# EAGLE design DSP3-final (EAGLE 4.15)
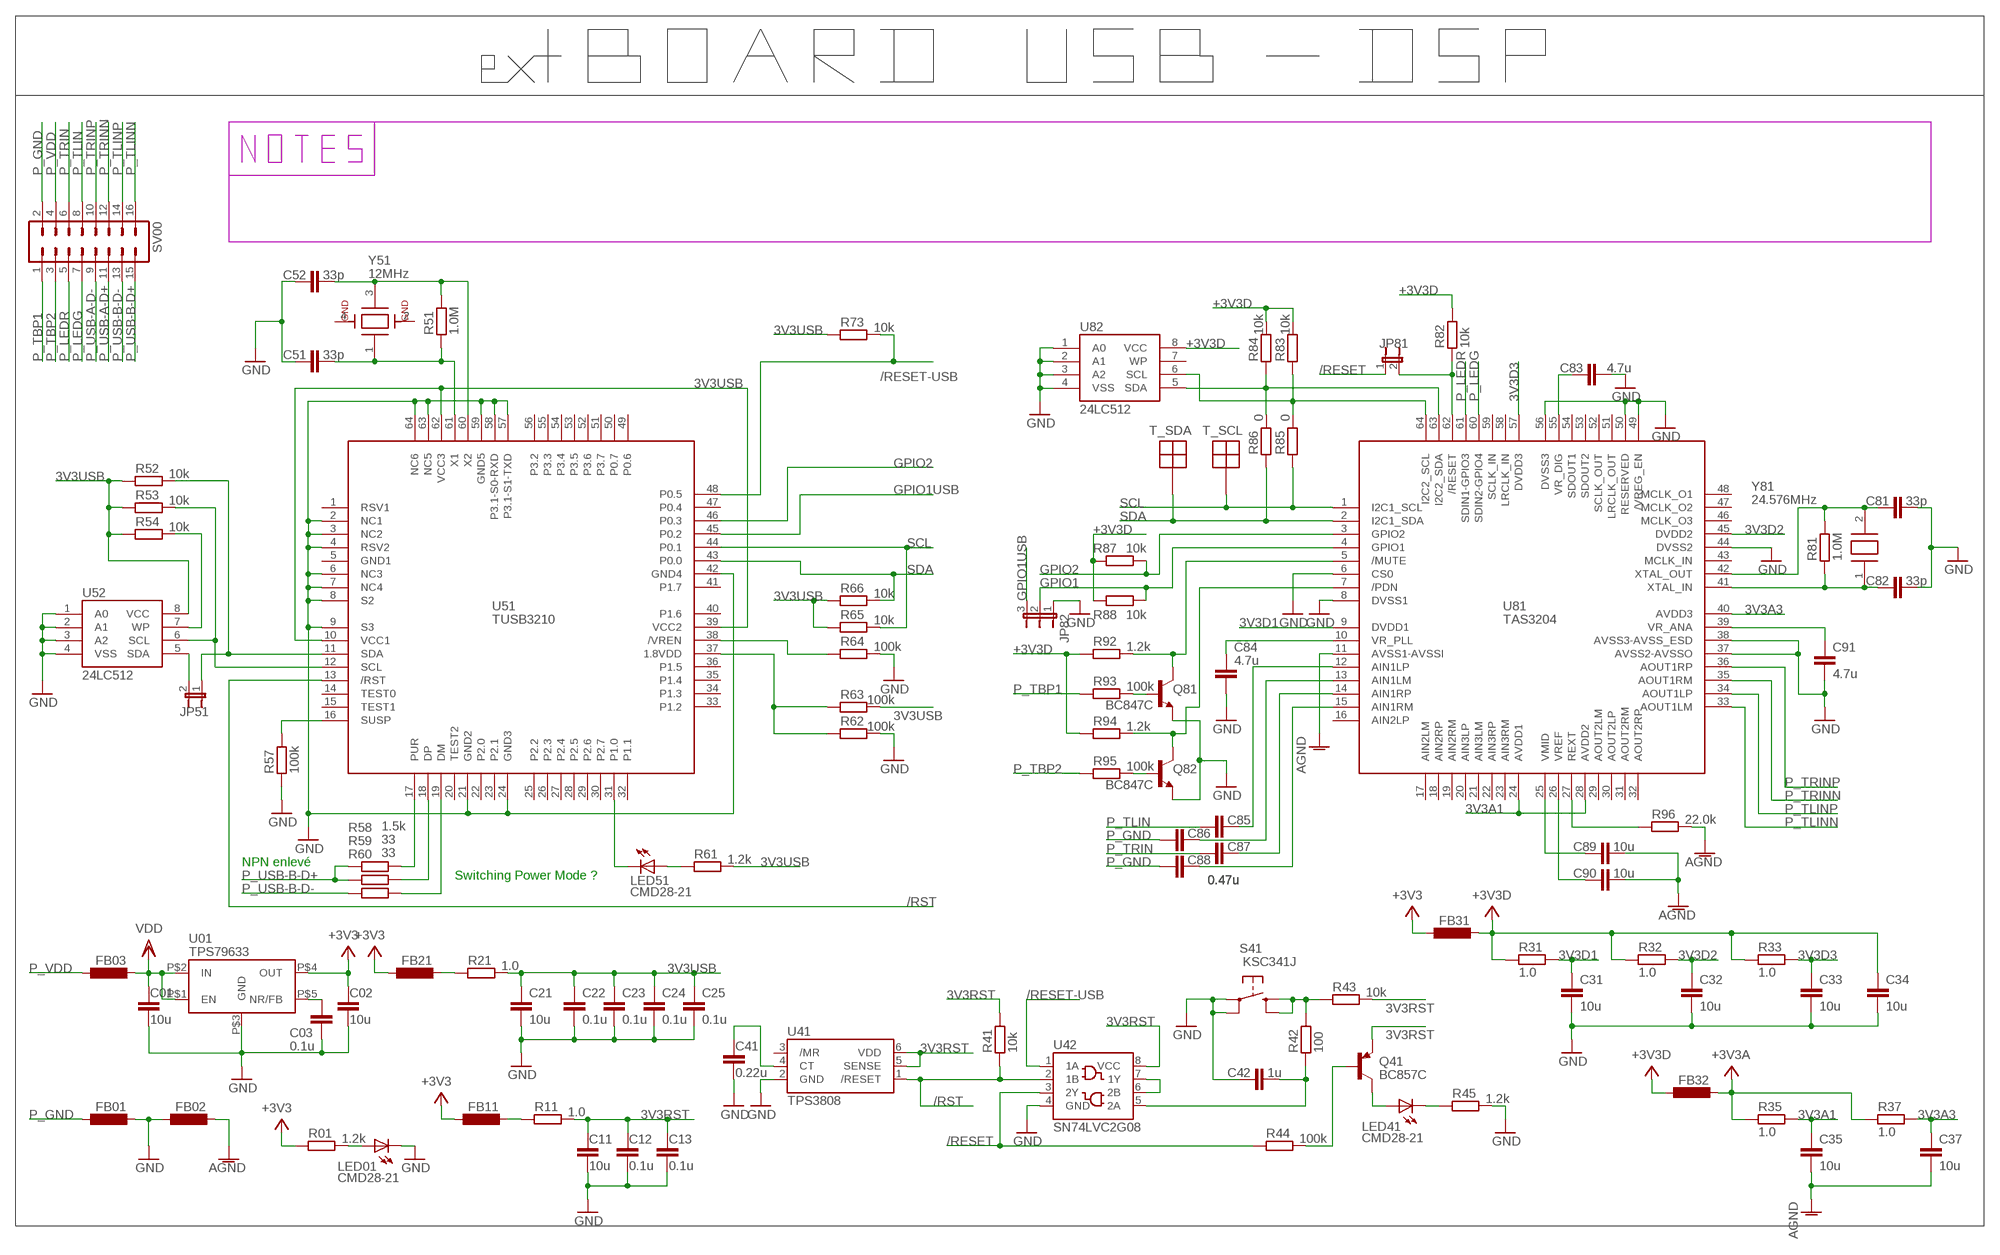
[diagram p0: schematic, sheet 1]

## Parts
C01  10u  C-EUC-EU-0603  [R0603]
C02  10u  C-EUC-EU-0603  [R0603]
C03  0.1u  C-EUC-EU-0603  [R0603]
C11  10u  C-EUC-EU-0603  [R0603]
C12  0.1u  C-EUC-EU-0603  [R0603]
C13  0.1u  C-EUC-EU-0603  [R0603]
C21  10u  C-EUC-EU-0603  [R0603]
C22  0.1u  C-EUC-EU-0603  [R0603]
C23  0.1u  C-EUC-EU-0603  [R0603]
C24  0.1u  C-EUC-EU-0603  [R0603]
C25  0.1u  C-EUC-EU-0603  [R0603]
C31  10u  C-EUC-EU-0603  [R0603]
C32  10u  C-EUC-EU-0603  [R0603]
C33  10u  C-EUC-EU-0603  [R0603]
C34  10u  C-EUC-EU-0603  [R0603]
C35  10u  C-EUC-EU-0603  [R0603]
C37  10u  C-EUC-EU-0603  [R0603]
C41  0.22u  C-EUC-EU-0603  [R0603]
C42  1u  C-EUC-EU-0603  [R0603]
C51  33p  C-EUC-EU-0603  [R0603]
C52  33p  C-EUC-EU-0603  [R0603]
C81  33p  C-EUC-EU-0603  [R0603]
C82  33p  C-EUC-EU-0603  [R0603]
C83  4.7u  C-EUC-EU-0603  [R0603]
C84  4.7u  C-EUC-EU-0603  [R0603]
C85  0.47u  C-EUC-EU-0603  [R0603]
C86  0.47u  C-EUC-EU-0603  [R0603]
C87  0.47u  C-EUC-EU-0603  [R0603]
C88  0.47u  C-EUC-EU-0603  [R0603]
C89  10u  C-EUC-EU-0603  [R0603]
C90  10u  C-EUC-EU-0603  [R0603]
C91  4.7u  C-EUC-EU-0603  [R0603]
FB01  L-EUFB-EU-1806  [FB1806]
FB02  L-EUFB-EU-1806  [FB1806]
FB03  L-EUFB-EU-1806  [FB1806]
FB11  L-EUFB-EU-1806  [FB1806]
FB21  L-EUFB-EU-1806  [FB1806]
FB31  L-EUFB-EU-1806  [FB1806]
FB32  L-EUFB-EU-1806  [FB1806]
JP51  JP1E  [JP1]
JP81  JP1E  [JP1]
JP82  JP2E  [JP2]
LED01  CMD28-21  [CMD28-21]
LED41  CMD28-21  [CMD28-21]
LED51  CMD28-21  [CMD28-21]
Q41  BC857C  BC857CSMD  [SOT23-BEC]
Q81  BC847C  BC847CSMD  [SOT23]
Q82  BC847C  BC847CSMD  [SOT23]
R01  1.2k  R-EUR-EU-0603  [R0603]
R11  1.0  R-EUR-EU-0603  [R0603]
R21  1.0  R-EUR-EU-0603  [R0603]
R31  1.0  R-EUR-EU-0603  [R0603]
R32  1.0  R-EUR-EU-0603  [R0603]
R33  1.0  R-EUR-EU-0603  [R0603]
R35  1.0  R-EUR-EU-0603  [R0603]
R37  1.0  R-EUR-EU-0603  [R0603]
R41  10k  R-EUR-EU-0603  [R0603]
R42  100  R-EUR-EU-0603  [R0603]
R43  10k  R-EUR-EU-0603  [R0603]
R44  100k  R-EUR-EU-0603  [R0603]
R45  1.2k  R-EUR-EU-0603  [R0603]
R51  1.0M  R-EUR-EU-0603  [R0603]
R52  10k  R-EUR-EU-0603  [R0603]
R53  10k  R-EUR-EU-0603  [R0603]
R54  10k  R-EUR-EU-0603  [R0603]
R57  100k  R-EUR-EU-0603  [R0603]
R58  1.5k  R-EUR-EU-0603  [R0603]
R59  33  R-EUR-EU-0603  [R0603]
R60  33  R-EUR-EU-0603  [R0603]
R61  1.2k  R-EUR-EU-0603  [R0603]
R62  100k  R-EUR-EU-0603  [R0603]
R63  100k  R-EUR-EU-0603  [R0603]
R64  100k  R-EUR-EU-0603  [R0603]
R65  10k  R-EUR-EU-0603  [R0603]
R66  10k  R-EUR-EU-0603  [R0603]
R73  10k  R-EUR-EU-0603  [R0603]
R81  1.0M  R-EUR-EU-0603  [R0603]
R82  10k  R-EUR-EU-0603  [R0603]
R83  10k  R-EUR-EU-0603  [R0603]
R84  10k  R-EUR-EU-0603  [R0603]
R85  0  R-EUR-EU-0603  [R0603]
R86  0  R-EUR-EU-0603  [R0603]
R87  10k  R-EUR-EU-0603  [R0603]
R88  10k  R-EUR-EU-0603  [R0603]
R92  1.2k  R-EUR-EU-0603  [R0603]
R93  100k  R-EUR-EU-0603  [R0603]
R94  1.2k  R-EUR-EU-0603  [R0603]
R95  100k  R-EUR-EU-0603  [R0603]
R96  22.0k  R-EUR-EU-0603  [R0603]
S41  KSC341J  [KSCTACTILEJ]
SV00  MA08-20.9MM  [MA08-2-0.9MM]
T_SCL  PICOT  [PICOT]
T_SDA  PICOT  [PICOT]
U01  TPS79633  TPS79633DDPAK-5  [DDPAK-5]
U41  TPS3808  TPS3808DBV  [SOT23-6]
U42  SN74LVC2G08  SN74LVC2G08DCT  [DCT8]
U51  TUSB3210  TUSB321010X10  [SQFP-S-10X10-64]
U52  24LC512  24LC512SOIC08SP  [SO08SP]
U81  TAS3204  TAS320410X10  [SQFP-S-10X10-64]
U82  24LC512  24LC512SOIC08SP  [SO08SP]
Y51  12MHz  ABMM2  [ABMM2]
Y81  24.576MHz  ABM3  [ABM3]

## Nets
3V3A1: C35.P$1 R35.P$2 U81.24(AVDD1) U81.28(AVDD2)
3V3A3: C37.P$1 R37.P$2 U81.40(AVDD3)
3V3D1: C31.P$1 R31.P$2 U81.9(DVDD1)
3V3D2: C32.P$1 R32.P$2 U81.45(DVDD2)
3V3D3: C33.P$1 R33.P$2 U81.57(DVDD3)
3V3RST: C11.P$1 C12.P$1 C13.P$1 Q41.E R11.P$2 R41.P$2 R43.P$2 U41.5(SENSE) U41.6(VDD) U42.8(VCC)
3V3USB: C21.P$1 C22.P$1 C23.P$1 C24.P$1 C25.P$1 R21.P$2 R52.P$1 R53.P$1 R54.P$1 R61.P$2 R63.P$2 R65.P$1 R66.P$1 R73.P$1 U51.10(VCC1) U51.39(VCC2) U51.62(VCC3) U52.8(VCC)
+3V3: C02.P$1 FB11.P$2 FB21.P$2 FB31.P$2 R01.P$1 U01.P$4(OUT)
+3V3A: FB32.P$1 R35.P$1 R37.P$1
+3V3D: C34.P$1 FB31.P$1 FB32.P$2 R31.P$1 R32.P$1 R33.P$1 R82.P$2 R83.P$2 R84.P$2 R87.P$1 R88.P$1 R92.P$1 R94.P$1 U82.8(VCC)
/RESET: JP81.1 R44.P$1 U42.3(2Y)
/RESET-USB: R73.P$2 U42.1(1A) U51.48(P0.5)
/RST: R41.P$1 U41.1(/RESET) U42.2(1B) U51.13(/RST)
AGND: C35.P$2 C37.P$2 C89.P$2 C90.P$2 FB02.P$1 R96.P$2 U81.11(AVSS1-AVSSI)
GND: C01.P$2 C02.P$2 C03.P$2 C11.P$2 C12.P$2 C13.P$2 C21.P$2 C22.P$2 C23.P$2 C24.P$2 C25.P$2 C31.P$2 C32.P$2 C33.P$2 C34.P$2 C41.P$2 C42.P$1 C51.P$1 C52.P$1 C81.P$2 C82.P$2 C83.P$2 C84.P$2 C91.P$2 FB01.P$1 FB02.P$2 JP82.1 LED01.P$1(C) Q81.2(E) Q82.2(E) R45.P$2 R57.P$1 R62.P$2 R64.P$2 S41.P$1(P) S41.P$4(P1) U01.P$3(GND) U41.2(GND) U42.4(GND) U51.2(NC1) U51.3(NC2) U51.4(RSV2) U51.6(NC3) U51.7(NC4) U51.8(S2) U51.9(S3) U51.21(GND2) U51.24(GND3) U51.42(GND4) U51.57(P3.1-S1-TXD) U51.58(P3.1-S0-RXD) U51.59(GND5) U51.63(NC5) U51.64(NC6) U52.1(A0) U52.2(A1) U52.3(A2) U52.4(VSS) U81.6(CS0) U81.8(DVSS1) U81.37(AVSS2-AVSSO) U81.38(AVSS3-AVSS_ESD) U81.44(DVSS2) U81.49(/VREG_EN) U81.50(RESERVED) U81.56(DVSS3) U82.1(A0) U82.2(A1) U82.3(A2) U82.4(VSS)
GPIO1: JP82.2 R88.P$2 U81.4(GPIO1)
GPIO1USB: JP82.3 U51.45(P0.2)
GPIO2: R87.P$2 U51.46(P0.3) U81.3(GPIO2)
N$1: C52.P$2 R51.P$2 U51.60(X2) Y51.3
N$2: JP51.1 R52.P$2 U51.11(SDA)
N$3: C51.P$2 R51.P$1 U51.61(X1) Y51.1
N$4: Q81.3(C) R92.P$2 U81.5(/MUTE)
N$6: R53.P$2 U51.12(SCL) U52.6(SCL)
N$7: R54.P$2 U52.7(WP)
N$8: R58.P$2 U51.17(PUR)
N$9: R59.P$2 U51.18(DP)
N$10: R60.P$2 U51.19(DM)
N$11: Q41.B R44.P$2
N$12: R96.P$1 U81.27(REXT)
N$13: R57.P$2 U51.16(SUSP)
N$14: LED51.P$1(C) U51.31(P1.0)
N$15: LED51.P$2(A) R61.P$1
N$16: R64.P$1 U51.38(/VREN)
N$17: R62.P$1 R63.P$1 U51.37(1.8VDD)
N$18: C41.P$1 U41.4(CT)
N$19: Q81.1(B) R93.P$2
N$20: Q82.1(B) R95.P$2
N$21: Q82.3(C) R94.P$2 U81.7(/PDN)
N$25: JP51.2 U52.5(SDA)
N$26: C03.P$1 U01.P$5(NR/FB)
N$29: C81.P$1 R81.P$2 U81.42(XTAL_OUT) Y81.2
N$31: C82.P$1 R81.P$1 U81.41(XTAL_IN) Y81.1
N$34: C84.P$1 U81.10(VR_PLL)
N$36: C91.P$1 U81.39(VR_ANA)
N$43: C83.P$1 U81.55(VR_DIG)
N$45: JP81.2 R82.P$1 U81.62(/RESET)
N$47: R84.P$1 R86.P$2 U81.63(I2C2_SDA) U82.5(SDA)
N$48: R83.P$1 R85.P$2 U81.64(I2C2_SCL) U82.6(SCL)
N$58: C89.P$1 U81.25(VMID)
N$59: C90.P$1 U81.26(VREF)
N$64: C85.P$1 U81.12(AIN1LP)
N$65: C86.P$1 U81.13(AIN1LM)
N$66: C87.P$1 U81.14(AIN1RP)
N$67: C88.P$1 U81.15(AIN1RM)
N$91: U42.6(2B) U42.7(1Y)
N$93: R42.P$2 R43.P$1 S41.P$2(S) S41.P$3(S1)
N$96: C42.P$2 R42.P$1 U42.5(2A)
N$98: LED41.P$2(A) Q41.C
N$99: LED41.P$1(C) R45.P$1
N$101: FB21.P$1 R21.P$1
N$110: LED01.P$2(A) R01.P$2
N$111: FB11.P$1 R11.P$1
P_GND: C86.P$2 C88.P$2 FB01.P$2 SV00.2
P_LEDG: SV00.7 U81.60(SDIN2-GPIO4)
P_LEDR: SV00.5 U81.61(SDIN1-GPIO3)
P_TBP1: R93.P$1 SV00.1
P_TBP2: R95.P$1 SV00.3
P_TLIN: C85.P$2 SV00.8
P_TLINN: SV00.16 U81.33(AOUT1LM)
P_TLINP: SV00.14 U81.34(AOUT1LP)
P_TRIN: C87.P$2 SV00.6
P_TRINN: SV00.12 U81.35(AOUT1RM)
P_TRINP: SV00.10 U81.36(AOUT1RP)
P_USB-A-D+: SV00.11
P_USB-A-D-: SV00.9
P_USB-B-D+: R58.P$1 R59.P$1 SV00.15
P_USB-B-D-: R60.P$1 SV00.13
P_VDD: FB03.P$2 SV00.4
SCL: R65.P$2 R85.P$1 T_SCL.P$1 U51.44(P0.1) U81.1(I2C1_SCL)
SDA: R66.P$2 R86.P$1 T_SDA.P$1 U51.43(P0.0) U81.2(I2C1_SDA)
VDD: C01.P$1 FB03.P$1 U01.P$1(EN) U01.P$2(IN)
Unconnected: U41.3(/MR) U51.1(RSV1) U51.5(GND1) U51.14(TEST0) U51.15(TEST1) U51.20(TEST2) U51.22(P2.0) U51.23(P2.1) U51.25(P2.2) U51.26(P2.3) U51.27(P2.4) U51.28(P2.5) U51.29(P2.6) U51.30(P2.7) U51.32(P1.1) U51.33(P1.2) U51.34(P1.3) U51.35(P1.4) U51.36(P1.5) U51.40(P1.6) U51.41(P1.7) U51.47(P0.4) U51.49(P0.6) U51.50(P0.7) U51.51(P3.7) U51.52(P3.6) U51.53(P3.5) U51.54(P3.4) U51.55(P3.3) U51.56(P3.2) U81.16(AIN2LP) U81.17(AIN2LM) U81.18(AIN2RP) U81.19(AIN2RM) U81.20(AIN3LP) U81.21(AIN3LM) U81.22(AIN3RP) U81.23(AIN3RM) U81.29(AOUT2LM) U81.30(AOUT2LP) U81.31(AOUT2RM) U81.32(AOUT2RP) U81.43(MCLK_IN) U81.46(MCLK_O3) U81.47(MCLK_O2) U81.48(MCLK_O1) U81.51(LRCLK_OUT) U81.52(SCLK_OUT) U81.53(SDOUT2) U81.54(SDOUT1) U81.58(LRCLK_IN) U81.59(SCLK_IN) U82.7(WP) Y51.2 Y51.4

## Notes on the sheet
- NPN enlevé
- Switching Power Mode ?

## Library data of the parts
C01-C03 C11-C13 C21-C25 C31-C35 C37 C41 C42 C51 C52 C81-C91 = 000perso:C-EU
FB01-FB03 FB11 FB21 FB31 FB32 = 000perso:L-EU
JP51 JP81 = 000perso:JP1E: JUMPER
JP82 = 000perso:JP2E: JUMPER
LED01 LED41 LED51 = 000perso:CMD28-21
Q41 = 000perso:BC857*: PNP Transistror
Q81 Q82 = 000perso:BC847*: NPN Transistor
R01 R11 R21 R31-R33 R35 R37 R41-R45 R51-R54 R57-R66 R73 R81-R88 R92-R96 = 000perso:R-EU
S41 = 000perso:KSC341J
SV00 = 000perso:MA08-2: PIN HEADER
T_SCL T_SDA = 000perso:PICOT
U01 = 000perso:TPS79633
U41 = 000perso:TPS3808
U42 = 000perso:SN74LVC2G08
U51 = 000perso:TUSB3210
U52 U82 = 000perso:24LC512
U81 = 000perso:TAS3204
Y51 = 000perso:ABMM2
Y81 = 000perso:ABM3

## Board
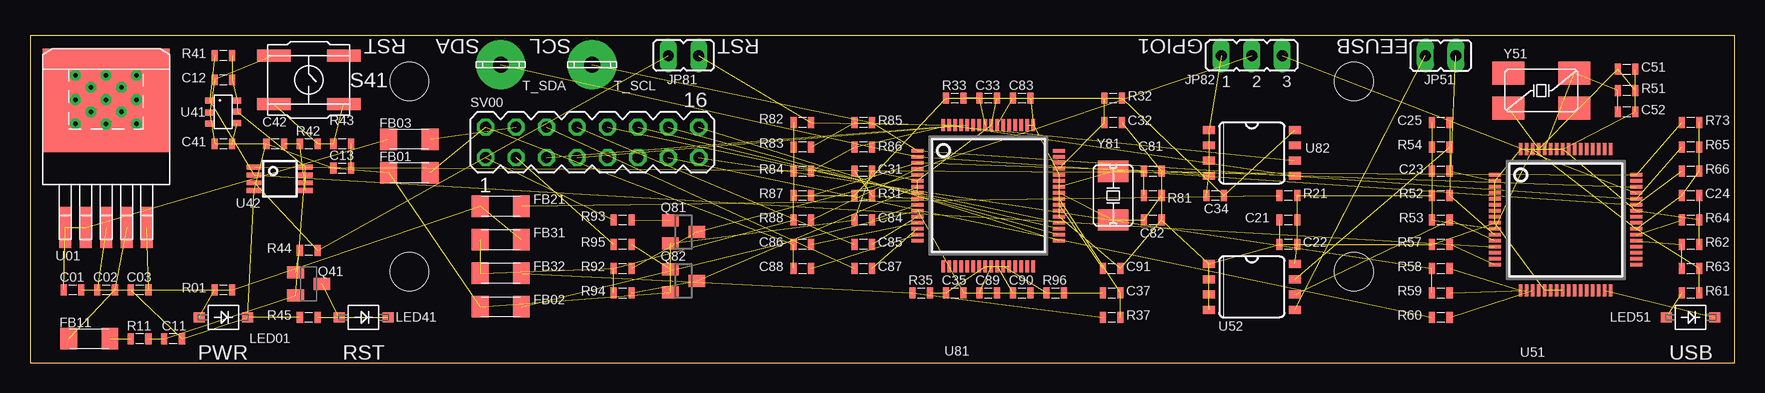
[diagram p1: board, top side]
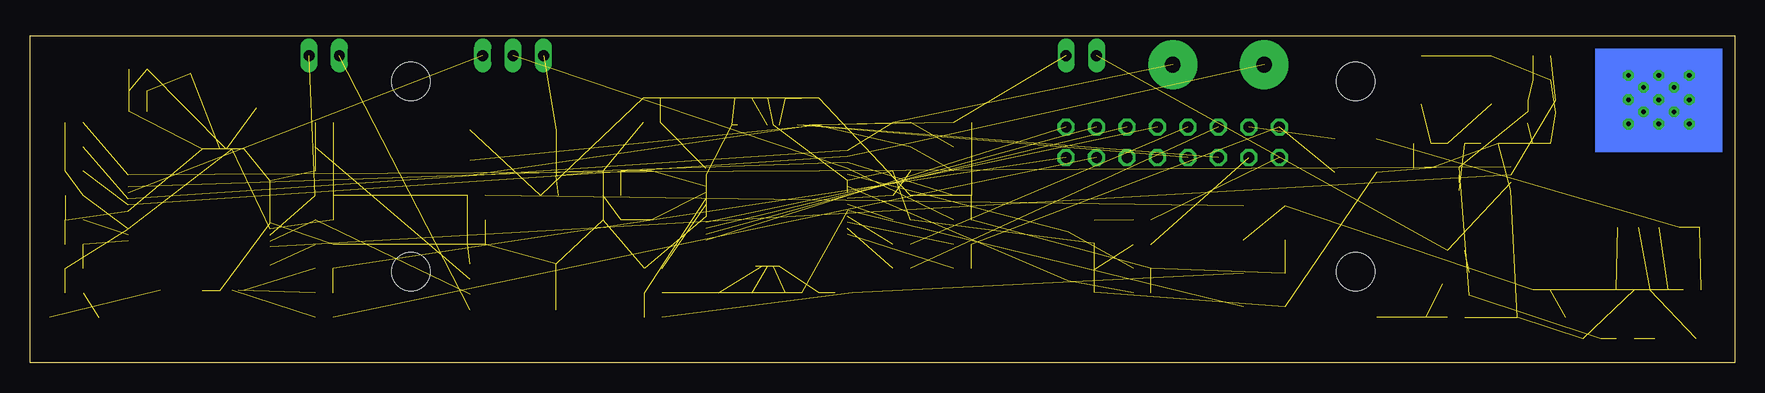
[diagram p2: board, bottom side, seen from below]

Size 142.12 x 27.31 mm. Coordinates in mm from the lower left corner, seen from the top.
Outline: 0,0 142.12,0 142.12,27.31 0,27.31 0,0
Copper layers (1*16): Top 0.035mm / dielectric 1.5mm / Bottom 0.035mm
Design rules "HPproto2": minimum track width 8mil, minimum drill 15mil, track to track 8mil, track to pad 8mil, pad to pad 7mil, via to via 20mil, smd to smd 8mil, copper to edge 40mil, drill to drill 16mil, minimum pad ring 10mil, minimum via ring 10mil, stop-mask expansion 4mil, vias tented up to drill 0mil, thermal gap 10mil
Holes 3.2 mm at 31.62,23.48 31.62,7.61 110.36,23.48 110.36,7.61
tRestrict: area 28.3,20.2 to 34.9,26.8; area 28.3,4.3 to 34.9,10.9; area 107.1,4.3 to 113.6,10.9; area 107.1,20.2 to 113.6,26.8
bRestrict: area 28.4,20.2 to 34.9,26.7; area 28.4,4.4 to 34.9,10.9; area 107.1,4.4 to 113.6,10.9; area 107.1,20.2 to 113.6,26.7
vRestrict: area 36.4,15.7 to 57.3,21.1

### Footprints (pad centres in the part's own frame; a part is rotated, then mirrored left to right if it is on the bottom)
R0603 = smd 0.508 x 0.914: P$1 -0.737,0; P$2 0.737,0
FB1806 = smd 1.397 x 1.778: P$1 -1.727,0; P$2 1.727,0
JP1 = drill 0.914 long: 1 0,-1.27; 2 0,1.27
JP2 = drill 0.914 long: 1 -2.54,0; 2 0,0; 3 2.54,0
CMD28-21 = smd 0.914 x 0.813: P$1 -2.032,0; P$2 2.032,0
SOT23-BEC = smd 1 x 1.4: B -0.95,-1.1; C 0,1.1; E 0.95,-1.1
SOT23 = smd 1 x 1.4: 1 -0.95,-1.1; 2 0.95,-1.1; 3 0,1.1
KSCTACTILEJ = smd 2.794 x 1.016: P$1 -2.921,2.032; P$2 -2.921,-2.032; P$3 2.921,-2.032; P$4 2.921,2.032
MA08-2-0.9MM = drill 0.9 pad 1.422 octagon: 1 -8.89,-1.27; 2 -8.89,1.27; 3 -6.35,-1.27; 4 -6.35,1.27; 5 -3.81,-1.27; 6 -3.81,1.27; 7 -1.27,-1.27; 8 -1.27,1.27; 9 1.27,-1.27; 10 1.27,1.27; 11 3.81,-1.27; 12 3.81,1.27; 13 6.35,-1.27; 14 6.35,1.27; 15 8.89,-1.27; 16 8.89,1.27
PICOT = drill 1.3 pad 4.064 round: P$1 0,0
DDPAK-5 = smd 1 x 3.4: P$1 -3.4,-6.6; P$2 -1.7,-6.6; P$3 0,-6.6; P$4 1.7,-6.6; P$5 3.4,-6.6 | smd 10.6 x 8.6: P$6 0,4
SOT23-6 = smd 0.5 x 0.7: 1 -0.95,-1.15; 2 0.05,-1.15; 3 1,-1.15; 4 0.95,1.15; 5 0,1.15; 6 -0.95,1.15
DCT8 = smd 0.4 x 1.2: 1 -0.975,-2.15; 2 -0.325,-2.15; 3 0.325,-2.15; 4 0.975,-2.15; 5 0.975,2.15; 6 0.325,2.15; 7 -0.325,2.15; 8 -0.975,2.15
SQFP-S-10X10-64 = smd 1 x 0.3: 1 -5.9,3.75; 2 -5.9,3.25; 3 -5.9,2.75; 4 -5.9,2.25; 5 -5.9,1.75; 6 -5.9,1.25; 7 -5.9,0.75; 8 -5.9,0.25; 9 -5.9,-0.25; 10 -5.9,-0.75; 11 -5.9,-1.25; 12 -5.9,-1.75; 13 -5.9,-2.25; 14 -5.9,-2.75; 15 -5.9,-3.25; 16 -5.9,-3.75; 33 5.9,-3.75; 34 5.9,-3.25; 35 5.9,-2.75; 36 5.9,-2.25; 37 5.9,-1.75; 38 5.9,-1.25; 39 5.9,-0.75; 40 5.9,-0.25; 41 5.9,0.25; 42 5.9,0.75; 43 5.9,1.25; 44 5.9,1.75; 45 5.9,2.25; 46 5.9,2.75; 47 5.9,3.25; 48 5.9,3.75 | smd 0.3 x 1: 17 -3.75,-5.9; 18 -3.25,-5.9; 19 -2.75,-5.9; 20 -2.25,-5.9; 21 -1.75,-5.9; 22 -1.25,-5.9; 23 -0.75,-5.9; 24 -0.25,-5.9; 25 0.25,-5.9; 26 0.75,-5.9; 27 1.25,-5.9; 28 1.75,-5.9; 29 2.25,-5.9; 30 2.75,-5.9; 31 3.25,-5.9; 32 3.75,-5.9; 49 3.75,5.9; 50 3.25,5.9; 51 2.75,5.9; 52 2.25,5.9; 53 1.75,5.9; 54 1.25,5.9; 55 0.75,5.9; 56 0.25,5.9; 57 -0.25,5.9; 58 -0.75,5.9; 59 -1.25,5.9; 60 -1.75,5.9; 61 -2.25,5.9; 62 -2.75,5.9; 63 -3.25,5.9; 64 -3.75,5.9
SO08SP = smd 0.66 x 1.016: 1 -1.905,-3.581; 2 -0.635,-3.581; 3 0.635,-3.581; 4 1.905,-3.581; 5 1.905,3.581; 6 0.635,3.581; 7 -0.635,3.581; 8 -1.905,3.581
ABMM2 = smd 2.667 x 1.905: 1 -2.731,-1.46; 2 2.731,-1.46; 3 2.731,1.46; 4 -2.731,1.46
ABM3 = smd 1.778 x 2.54: 1 -2.032,0; 2 2.032,0

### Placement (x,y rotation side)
C01  3.55,6.08 0 top
C02  6.34,6.08 180 top
C03  9.14,6.08 180 top
C11  11.93,2.02 0 top
C12  16.12,23.61 180 top
C13  26.03,16.24 180 top
C21  104.9,11.93 180 top
C22  104.9,9.89 180 top
C23  117.6,15.99 0 top
C24  138.43,13.96 0 top
C25  117.6,20.05 0 top
C31  69.46,15.99 0 top
C32  90.29,20.05 0 top
C33  79.88,22.09 0 top
C34  98.8,13.96 180 top
C35  77.08,5.83 0 top
C37  90.17,5.83 180 top
C41  16.12,18.28 180 top
C42  20.44,18.28 0 top
C51  133.09,24.5 180 top
C52  133.09,20.94 180 top
C81  93.59,15.99 0 top
C82  93.59,11.93 0 top
C83  82.67,22.09 0 top
C84  69.46,11.93 180 top
C85  69.46,9.89 180 top
C86  64.38,9.89 180 top
C87  69.46,7.86 180 top
C88  64.38,7.86 180 top
C89  79.88,5.83 0 top
C90  82.67,5.83 0 top
C91  90.17,7.86 0 top
FB01  31.62,15.86 0 top
FB02  39.24,4.69 180 top
FB03  31.62,18.66 0 top
FB11  4.95,2.02 180 top
FB21  39.24,13.07 180 top
FB31  39.24,10.27 0 top
FB32  39.24,7.48 180 top
JP51  117.6,25.64 90 top
JP81  54.48,25.64 270 top
JP82  101.85,25.64 0 top
LED01  16.12,3.8 180 top
LED41  27.81,3.8 180 top
LED51  138.43,3.8 180 top
Q41  23.24,6.59 270 top
Q81  54.48,10.91 270 top
Q82  54.48,6.85 270 top
R01  16.12,6.08 180 top
R11  9.14,2.02 0 top
R21  104.9,13.96 0 top
R31  69.46,13.96 0 top
R32  90.29,22.09 180 top
R33  77.08,22.09 0 top
R35  74.29,5.83 0 top
R37  90.17,3.8 0 top
R41  16.12,25.64 0 top
R42  23.24,18.28 0 top
R43  26.03,18.28 0 top
R44  23.24,9.39 180 top
R45  23.24,3.8 180 top
R51  133.09,22.72 180 top
R52  117.6,13.96 0 top
R53  117.6,11.93 0 top
R54  117.6,18.02 0 top
R57  117.6,9.89 0 top
R58  117.6,7.86 0 top
R59  117.6,5.83 0 top
R60  117.6,3.8 0 top
R61  138.43,5.83 0 top
R62  138.43,9.89 0 top
R63  138.43,7.86 0 top
R64  138.43,11.93 0 top
R65  138.43,18.02 180 top
R66  138.43,15.99 180 top
R73  138.43,20.05 180 top
R81  93.59,13.96 180 top
R82  64.38,20.05 180 top
R83  64.38,18.02 180 top
R84  64.38,15.99 180 top
R85  69.46,20.05 180 top
R86  69.46,18.02 180 top
R87  64.38,13.96 0 top
R88  64.38,11.93 0 top
R92  49.4,7.86 0 top
R93  49.4,11.93 0 top
R94  49.4,5.83 0 top
R95  49.4,9.89 0 top
R96  85.47,5.83 0 top
S41  23.24,23.61 0 top
SV00  46.86,18.4 0 top
T_SCL  46.86,24.88 0 top
T_SDA  39.24,24.88 0 top
U01  6.34,17.89 0 top
U41  16.12,20.94 270 top
U42  20.82,15.35 270 top
U51  128.01,11.93 0 top
U52  101.85,6.34 270 top
U81  79.88,13.96 0 top
U82  101.85,17.51 270 top
Y51  125.98,22.72 0 top
Y81  90.29,13.96 90 top

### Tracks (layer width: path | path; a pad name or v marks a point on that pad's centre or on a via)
3V3A1  (3 unrouted)
3V3A3  (2 unrouted)
3V3D1  (2 unrouted)
3V3D2  (2 unrouted)
3V3D3  (2 unrouted)
3V3RST  (9 unrouted)
3V3USB  (17 unrouted)
+3V3  (5 unrouted)
+3V3A  (2 unrouted)
+3V3D  (13 unrouted)
/RESET  (2 unrouted)
/RESET-USB  (2 unrouted)
/RST  (3 unrouted)
AGND  (6 unrouted)
GND  (69 unrouted)
GPIO1  (2 unrouted)
GPIO1USB  (1 unrouted)
GPIO2  (2 unrouted)
N$1  (3 unrouted)
N$2  (2 unrouted)
N$3  (3 unrouted)
N$4  (2 unrouted)
N$5  (via drill 0.38)
  other vias: 3.8,23.99
N$6  (2 unrouted)
N$7  (1 unrouted)
N$8  (1 unrouted)
N$9  (1 unrouted)
N$10  (1 unrouted)
N$11  (1 unrouted)
N$12  (1 unrouted)
N$13  (1 unrouted)
N$14  (1 unrouted)
N$15  (1 unrouted)
N$16  (1 unrouted)
N$17  (2 unrouted)
N$18  (1 unrouted)
N$19  (1 unrouted)
N$20  (1 unrouted)
N$21  (2 unrouted)
N$22  (via drill 0.38)
  other vias: 8.88,23.99
N$23  (via drill 0.38)
  other vias: 8.88,19.93
N$24  (via drill 0.38)
  other vias: 3.8,19.93
N$25  (1 unrouted)
N$26  (1 unrouted)
N$27  (via drill 0.38)
  other vias: 3.8,21.96
N$28  (via drill 0.38)
  other vias: 6.34,19.93
N$29  (3 unrouted)
N$30  (via drill 0.38)
  other vias: 6.34,21.96
N$31  (3 unrouted)
N$32  (via drill 0.38)
  other vias: 6.34,23.99
N$33  (via drill 0.38)
  other vias: 8.88,21.96
N$34  (1 unrouted)
N$35  (via drill 0.38)
  other vias: 5.08,22.97
N$36  (1 unrouted)
N$37  (via drill 0.38)
  other vias: 7.62,22.97
N$38  (via drill 0.38)
  other vias: 7.62,20.94
N$39  (via drill 0.38)
  other vias: 5.08,20.94
N$43  (1 unrouted)
N$45  (2 unrouted)
N$47  (3 unrouted)
N$48  (3 unrouted)
N$58  (1 unrouted)
N$59  (1 unrouted)
N$64  (1 unrouted)
N$65  (1 unrouted)
N$66  (1 unrouted)
N$67  (1 unrouted)
N$91  (1 unrouted)
N$93  (3 unrouted)
N$96  (2 unrouted)
N$98  (1 unrouted)
N$99  (1 unrouted)
N$101  (1 unrouted)
N$110  (1 unrouted)
N$111  (1 unrouted)
P_GND  (3 unrouted)
P_LEDG  (1 unrouted)
P_LEDR  (1 unrouted)
P_TBP1  (1 unrouted)
P_TBP2  (1 unrouted)
P_TLIN  (1 unrouted)
P_TLINN  (1 unrouted)
P_TLINP  (1 unrouted)
P_TRIN  (1 unrouted)
P_TRINN  (1 unrouted)
P_TRINP  (1 unrouted)
P_USB-B-D+  (2 unrouted)
P_USB-B-D-  (1 unrouted)
P_VDD  (1 unrouted)
SCL  (4 unrouted)
SDA  (4 unrouted)
VDD  (3 unrouted)
(copper drawn outside any net)
  shapes: Bottom area x1

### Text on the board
tNames: RST | SDA | SCL | RST | GPIO1 | EEUSB | PWR | RST | USB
